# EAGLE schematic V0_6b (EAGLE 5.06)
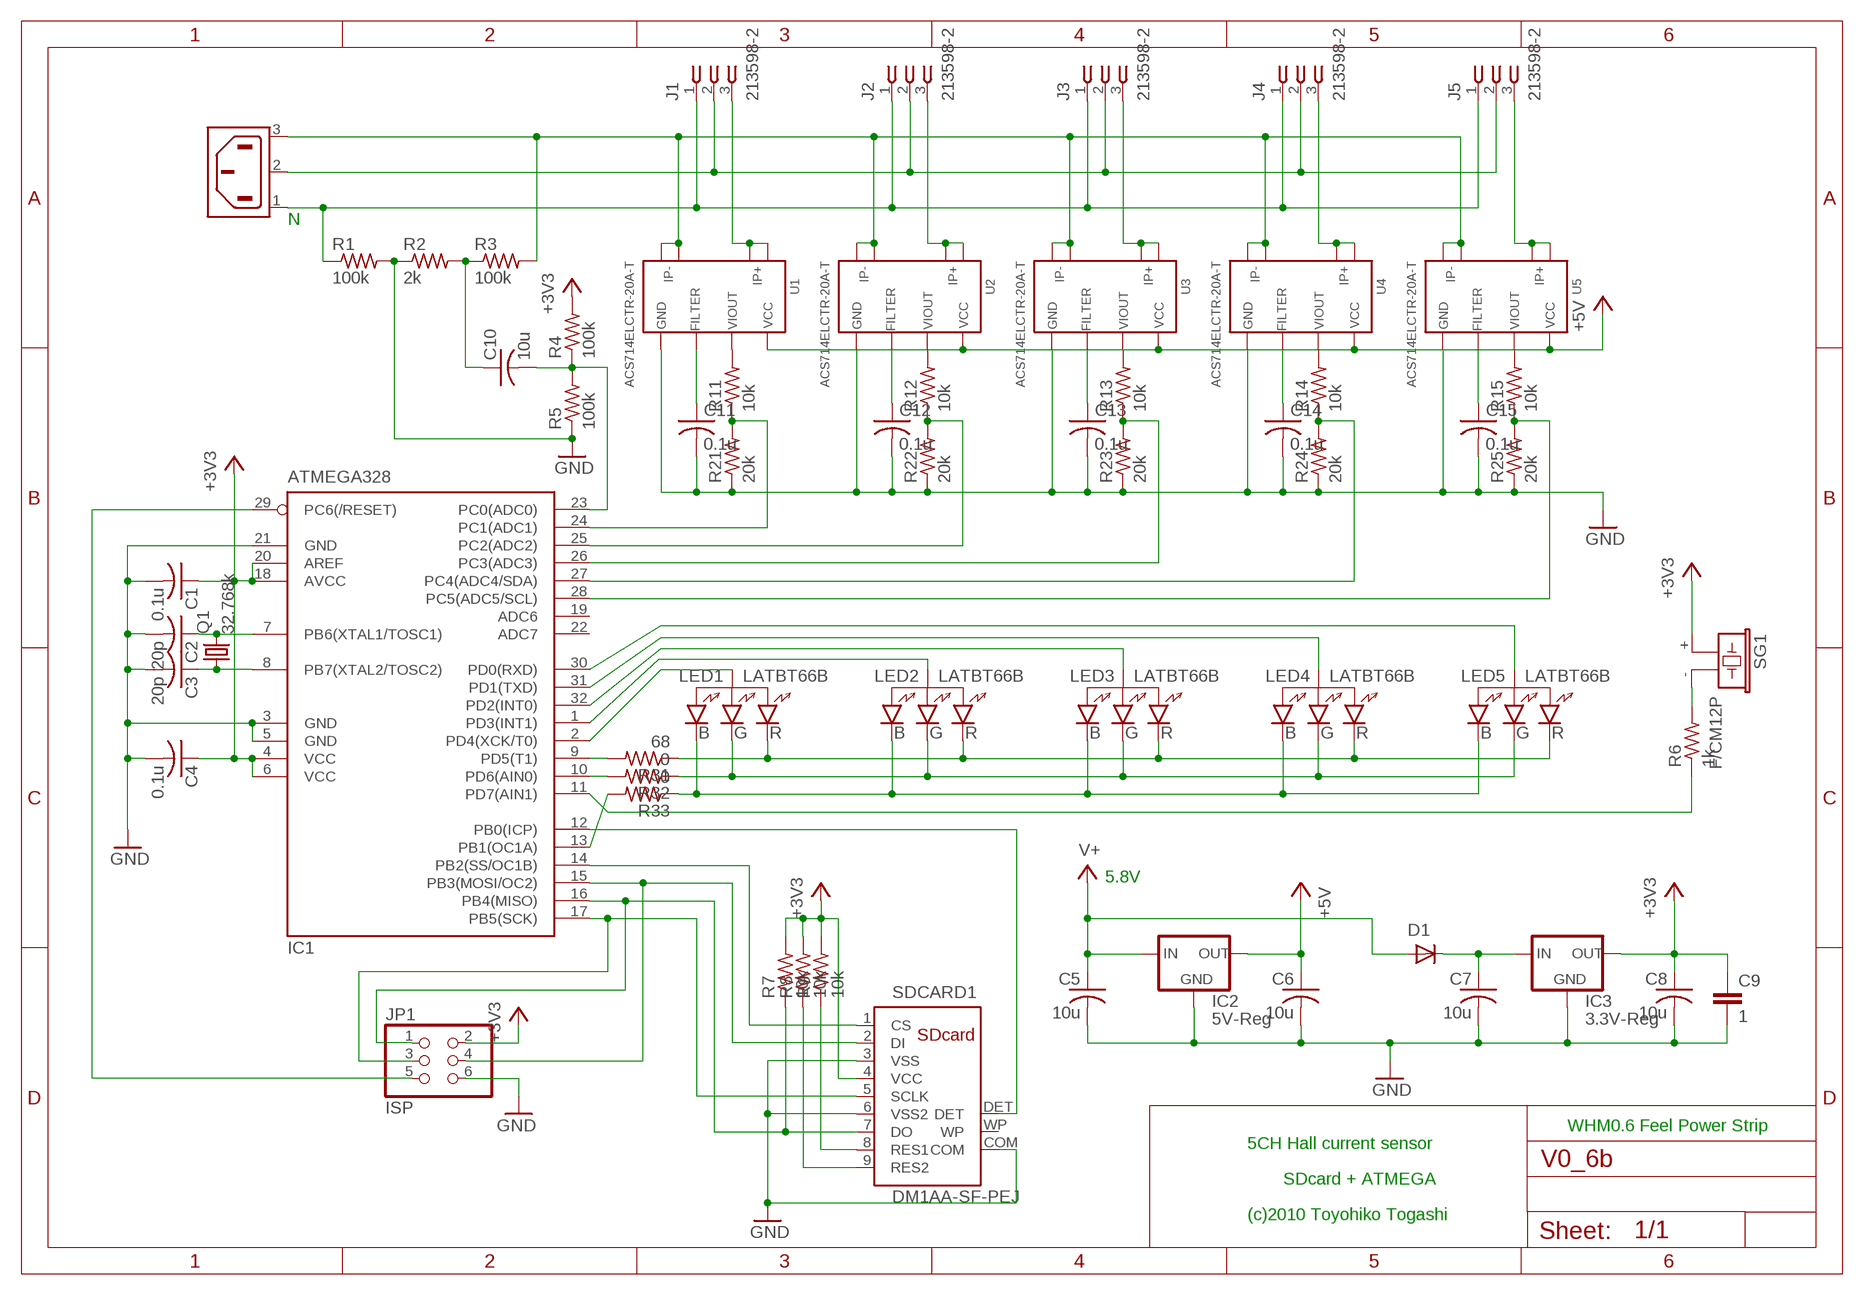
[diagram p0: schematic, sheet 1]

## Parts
C1  0.1u  C-USC0603  [C0603]
C2  20p  C-USC0603  [C0603]
C3  20p  C-USC0603  [C0603]
C4  0.1u  C-USC0603  [C0603]
C5  10u  C-USC0603  [C0603]
C6  10u  C-USC0603  [C0603]
C7  10u  C-USC0603  [C0603]
C8  10u  C-USC0603  [C0603]
C9  1  C7.5/4  [C7.5B4]
C10  10u  C-USC1206  [C1206]
C11  0.1u  C-USC0603  [C0603]
C12  0.1u  C-USC0603  [C0603]
C13  0.1u  C-USC0603  [C0603]
C14  0.1u  C-USC0603  [C0603]
C15  0.1u  C-USC0603  [C0603]
D1  GF1  [SMA-DO214AC]
IC1  ATMEGA328  MEGA8-AI  [TQFP32-08]
IC2  5V-Reg  XC63FPM  [SOT23]
IC3  3.3V-Reg  XC63FPM  [SOT23]
J1  213598-2  [213598-2]
J2  213598-2  [213598-2]
J3  213598-2  [213598-2]
J4  213598-2  [213598-2]
J5  213598-2  [213598-2]
JP1  ISP  PINHD-2X3  [2X03]
LED1  LATBT66B  [P-LCC-4]
LED2  LATBT66B  [P-LCC-4]
LED3  LATBT66B  [P-LCC-4]
LED4  LATBT66B  [P-LCC-4]
LED5  LATBT66B  [P-LCC-4]
Q1  32.768k  CRYSTALHC49UP  [HC49UP]
R1  100k  R-US_R0603  [R0603]
R2  2k  R-US_R0603  [R0603]
R3  100k  R-US_R0603  [R0603]
R4  100k  R-US_R0603  [R0603]
R5  100k  R-US_R0603  [R0603]
R6  1k  R-US_R0603  [R0603]
R7  10k  R-US_R0603  [R0603]
R8  10k  R-US_R0603  [R0603]
R9  10k  R-US_R0603  [R0603]
R11  10k  R-US_R0603  [R0603]
R12  10k  R-US_R0603  [R0603]
R13  10k  R-US_R0603  [R0603]
R14  10k  R-US_R0603  [R0603]
R15  10k  R-US_R0603  [R0603]
R21  20k  R-US_R0603  [R0603]
R22  20k  R-US_R0603  [R0603]
R23  20k  R-US_R0603  [R0603]
R24  20k  R-US_R0603  [R0603]
R25  20k  R-US_R0603  [R0603]
R31  68  R-US_R0603  [R0603]
R32  0  R-US_R0603  [R0603]
R33  0  R-US_R0603  [R0603]
SDCARD1  DM1AA-SF-PEJ  [DM1AA]
SG1  F/CM12P  [F/CM12P]
U1  ACS714ELCTR-20A-T  [SOP8]
U2  ACS714ELCTR-20A-T  [SOP8]
U3  ACS714ELCTR-20A-T  [SOP8]
U4  ACS714ELCTR-20A-T  [SOP8]
U5  ACS714ELCTR-20A-T  [SOP8]
X1  6ESRM-P  [6ESRM-P]

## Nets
+3V3: C1.1 C4.1 C8.1 C9.1 IC1.4(VCC) IC1.6(VCC) IC1.18(AVCC) IC1.20(AREF) IC3.2(OUT) JP1.2 R4.2 R7.2 R8.2 R9.2 SDCARD1.4(VCC) SG1.+
+5V: C6.1 IC2.2(OUT) U1.P$8(VCC) U2.P$8(VCC) U3.P$8(VCC) U4.P$8(VCC) U5.P$8(VCC)
GND: C1.2 C2.2 C3.2 C4.2 C5.2 C6.2 C7.2 C8.2 C9.2 C11.2 C12.2 C13.2 C14.2 C15.2 IC1.3(GND) IC1.5(GND) IC1.21(GND) IC2.1(GND) IC3.1(GND) JP1.6 R1.2 R2.1 R5.1 R21.1 R22.1 R23.1 R24.1 R25.1 SDCARD1.3(VSS) SDCARD1.6(VSS2) SDCARD1.COM U1.P$5(GND) U2.P$5(GND) U3.P$5(GND) U4.P$5(GND) U5.P$5(GND)
N$1: C10.2 IC1.23(PC0(ADC0)) R4.1 R5.2
N$2: R12.2 U2.P$7(VIOUT)
N$3: R13.2 U3.P$7(VIOUT)
N$4: R14.2 U4.P$7(VIOUT)
N$5: IC1.25(PC2(ADC2)) R12.1 R22.2
N$6: R11.2 U1.P$7(VIOUT)
N$7: C2.1 IC1.7(PB6(XTAL1/TOSC1)) Q1.2
N$8: IC1.24(PC1(ADC1)) R11.1 R21.2
N$9: IC1.29(PC6(/RESET)) JP1.5
N$10: IC1.9(PD5(T1)) R31.2
N$11: C3.1 IC1.8(PB7(XTAL2/TOSC2)) Q1.1
N$12: C12.1 U2.P$6(FILTER)
N$13: C11.1 U1.P$6(FILTER)
N$14: C13.1 U3.P$6(FILTER)
N$15: IC1.2(PD4(XCK/T0)) LED1.P$2
N$16: C14.1 U4.P$6(FILTER)
N$17: IC1.17(PB5(SCK)) JP1.3 SDCARD1.5(SCLK)
N$18: J2.3 U2.P$1(IP+1) U2.P$2(IP+2)
N$19: J3.3 U3.P$1(IP+1) U3.P$2(IP+2)
N$20: J4.3 U4.P$1(IP+1) U4.P$2(IP+2)
N$21: IC1.11(PD7(AIN1)) R6.1
N$22: J1.3 U1.P$1(IP+1) U1.P$2(IP+2)
N$23: IC1.1(PD3(INT1)) LED2.P$2
N$24: IC1.32(PD2(INT0)) LED3.P$2
N$25: IC1.31(PD1(TXD)) LED4.P$2
N$26: R6.2 SG1.-
N$27: R15.2 U5.P$7(VIOUT)
N$28: LED1.P$1 LED2.P$1 LED3.P$1 LED4.P$1 LED5.P$1 R31.1
N$29: J1.1 J2.1 J3.1 J4.1 J5.1 R1.1 X1.1(AC1)
N$30: LED1.P$4 LED2.P$4 LED3.P$4 LED4.P$4 LED5.P$4 R32.1
N$31: LED1.P$3 LED2.P$3 LED3.P$3 LED4.P$3 LED5.P$3 R33.1
N$32: IC1.15(PB3(MOSI/OC2)) JP1.4 SDCARD1.2(DI)
N$33: IC1.16(PB4(MISO)) JP1.1 R7.1 SDCARD1.7(DO)
N$34: J1.2 J2.2 J3.2 J4.2 J5.2 X1.2(SH)
N$35: IC1.13(PB1(OC1A)) R33.2
N$39: IC1.14(PB2(SS/OC1B)) SDCARD1.1(CS)
N$40: R3.2 U1.P$3(IP-1) U1.P$4(IP-2) U2.P$3(IP-1) U2.P$4(IP-2) U3.P$3(IP-1) U3.P$4(IP-2) U4.P$3(IP-1) U4.P$4(IP-2) U5.P$3(IP-1) U5.P$4(IP-2) X1.3(AC2)
N$41: R8.1 SDCARD1.9(RES2)
N$42: R9.1 SDCARD1.8(RES1)
N$43: IC1.12(PB0(ICP)) SDCARD1.DET
N$44: J5.3 U5.P$1(IP+1) U5.P$2(IP+2)
N$45: C15.1 U5.P$6(FILTER)
N$46: IC1.30(PD0(RXD)) LED5.P$2
N$47: IC1.10(PD6(AIN0)) R32.2
N$48: C10.1 R2.2 R3.1
N$52: IC1.26(PC3(ADC3)) R13.1 R23.2
N$53: IC1.27(PC4(ADC4/SDA)) R14.1 R24.2
N$54: IC1.28(PC5(ADC5/SCL)) R15.1 R25.2
N$56: C7.1 D1.K(C) IC3.3(IN)
V+: C5.1 D1.A IC2.3(IN)
Unconnected: IC1.19(ADC6) IC1.22(ADC7) SDCARD1.WP

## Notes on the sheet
- N
- 5.8V
- WHM0.6 Feel Power Strip
- 5CH Hall current sensor
- SDcard + ATMEGA
- (c)2010 Toyohiko Togashi

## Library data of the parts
C1-C8 C10-C15 = rcl:C-US: CAPACITOR, American symbol
C9 = capacitor-wima:C: CAPACITOR
D1 = diode:GF1: DIODE
IC1 = atmel:MEGA8: MICROCONTROLLER 8 Kbytes FLASH, 1 kbytes SRAM, 512 bytes EEPROM, USART, 6-channel 10 bit ADC, 2-channel 8 bit ADC Pin compatible with Atmega48, ATMega88, ATMega168 Source: avr.lbr
IC2 IC3 = v-reg:XC63FP: Positiv Voltage Regulators www.torex.co.jp/english/product/pro02/pdf/0201_xc62fp.pdf
J1-J5 = con-amp:213598-2: AC Jack Source: ENG_CD_213598_M.pdf
JP1 = pinhead:PINHD-2X3: PIN HEADER
LED1-LED5 = TOG:LATBT66B: RGB LED SMD
Q1 = crystal:CRYSTAL: CRYSTAL
R1-R9 R11-R15 R21-R25 R31-R33 = rcl:R-US_: RESISTOR, American symbol
SDCARD1 = TOG:DM1AA-SF-PEJ: SDcard connector HIROSE
SG1 = buzzer:F/CM12P: BUZZER
U1-U5 = TOG:ACS714
X1 = con-tycoelectronics:6ESRM-P: AC Connector 120/250 VAC Source: http://catalog.tycoelectronics.com .. ENG_DS_1654001_1099_SR_0406.pdf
